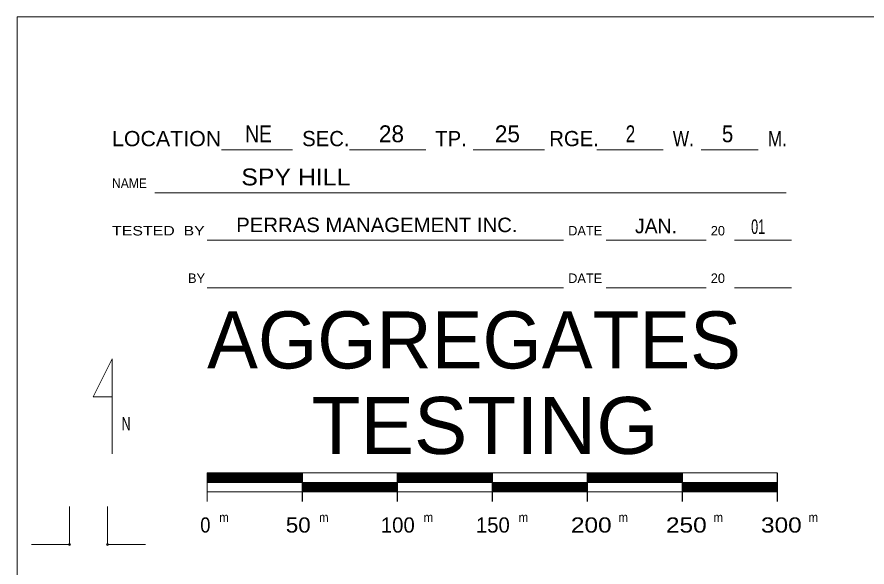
# Model space of a CAD drawing. Extents: x -496 to 480, y -452 to 700.
# Drawn here: x -450 to -2.8, y 410.5 to 700 of the extents above; entities that cross this region are included whole.
import ezdxf
from ezdxf.enums import TextEntityAlignment as Align

# ---------------------------------------------------------------- set-up
doc = ezdxf.new("R2010")
doc.units = 0
doc.header["$LTSCALE"] = 2
doc.header["$PDMODE"] = 32
doc.header["$PDSIZE"] = 1
doc.layers.add('3', color=7, linetype='Continuous', lineweight=13)

msp = doc.modelspace()

# ---------------------------------------------------------------- linework, layer by layer
at = {"layer": '3'}
for p, q in [((-342.517, 629.973), (-305.017, 629.973)), ((-275.017, 629.973), (-235.017, 629.973)), ((-210.017, 629.973), (-172.517, 629.973)), ((-145.017, 629.973), (-110.017, 629.973)), ((-90.017, 629.973), (-60.017, 629.973)), ((-377.517, 607.473), (-45.359, 607.473)), ((-350.017, 582.473), (-162.517, 582.473)), ((-140.017, 582.473), (-87.517, 582.473)), ((-72.517, 582.473), (-42.517, 582.473)), ((-350.017, 557.473), (-162.517, 557.473)), ((-140.017, 557.473), (-87.517, 557.473)), ((-72.517, 557.473), (-42.517, 557.473)), ((-350.017, 459.973), (-350.017, 444.973)), ((-50.017, 459.973), (-350.017, 459.973)), ((-350.017, 454.973), (-50.017, 454.973)), ((-422.391, 422.339), (-422.391, 442.339)), ((-402.391, 422.339), (-402.391, 442.339)), ((-422.391, 422.339), (-442.391, 422.339))]:
    msp.add_line(p, q, dxfattribs=at)
at = {"layer": '3', "lineweight": 25}
for p, q in [((-350.017, 459.473), (-300.017, 459.473)), ((-350.017, 458.973), (-300.017, 458.973)), ((-350.017, 458.473), (-300.017, 458.473)), ((-350.017, 457.973), (-300.017, 457.973)), ((-350.017, 457.473), (-300.017, 457.473)), ((-350.017, 456.973), (-300.017, 456.973)), ((-350.017, 456.473), (-300.017, 456.473)), ((-350.017, 456.473), (-300.017, 456.473)), ((-350.017, 456.473), (-300.017, 456.473)), ((-300.017, 459.973), (-300.017, 444.973)), ((-250.017, 459.973), (-250.017, 444.973)), ((-250.017, 459.473), (-200.017, 459.473)), ((-250.017, 458.973), (-200.017, 458.973)), ((-250.017, 458.473), (-200.017, 458.473)), ((-250.017, 457.973), (-200.017, 457.973)), ((-250.017, 457.473), (-200.017, 457.473)), ((-250.017, 456.973), (-200.017, 456.973)), ((-250.017, 456.473), (-200.017, 456.473)), ((-200.017, 459.973), (-200.017, 444.973)), ((-150.017, 459.973), (-150.017, 444.973)), ((-150.017, 459.473), (-100.017, 459.473)), ((-150.017, 458.973), (-100.017, 458.973)), ((-150.017, 458.473), (-100.017, 458.473)), ((-150.017, 457.973), (-100.017, 457.973)), ((-150.017, 457.473), (-100.017, 457.473)), ((-150.017, 456.973), (-100.017, 456.973)), ((-150.017, 456.473), (-100.017, 456.473)), ((-100.017, 459.973), (-100.017, 444.973)), ((-50.017, 459.973), (-50.017, 444.973)), ((-350.017, 455.973), (-300.017, 455.973)), ((-350.017, 455.973), (-300.017, 455.973)), ((-350.017, 455.473), (-300.017, 455.473)), ((-300.017, 454.473), (-250.017, 454.473)), ((-300.017, 453.973), (-250.017, 453.973)), ((-300.017, 453.473), (-250.017, 453.473)), ((-300.017, 452.973), (-250.017, 452.973)), ((-300.017, 452.473), (-250.017, 452.473)), ((-300.017, 451.973), (-250.017, 451.973)), ((-250.017, 455.973), (-200.017, 455.973)), ((-250.017, 455.473), (-200.017, 455.473)), ((-200.017, 454.473), (-150.017, 454.473)), ((-200.017, 453.973), (-150.017, 453.973)), ((-200.017, 453.473), (-150.017, 453.473)), ((-200.017, 452.973), (-150.017, 452.973)), ((-200.017, 452.473), (-150.017, 452.473)), ((-200.017, 451.973), (-150.017, 451.973)), ((-150.017, 455.973), (-100.017, 455.973)), ((-150.017, 455.473), (-100.017, 455.473)), ((-100.017, 454.473), (-50.017, 454.473)), ((-100.017, 453.973), (-50.017, 453.973)), ((-100.017, 453.473), (-50.017, 453.473)), ((-100.017, 452.973), (-50.017, 452.973)), ((-100.017, 452.473), (-50.017, 452.473)), ((-100.017, 451.973), (-50.017, 451.973)), ((-300.017, 451.473), (-250.017, 451.473)), ((-300.017, 450.973), (-250.017, 450.973)), ((-300.017, 450.473), (-250.017, 450.473)), ((-200.017, 451.473), (-150.017, 451.473)), ((-200.017, 450.973), (-150.017, 450.973)), ((-200.017, 450.473), (-150.017, 450.473)), ((-100.017, 451.473), (-50.017, 451.473)), ((-100.017, 450.973), (-50.017, 450.973)), ((-100.017, 450.473), (-50.017, 450.473))]:
    msp.add_line(p, q, dxfattribs=at)
at = {"layer": '3'}
for points in [[(449.983, -450.027), (449.983, 399.973), (449.983, 699.973), (-450.017, 699.973), (-450.017, 49.973), (-450.017, -450.027)], [(-400.017, 469.973), (-400.017, 519.973), (-410.017, 499.973), (-400.017, 499.973)], [(-350.017, 449.973), (-50.017, 449.973), (-50.017, 459.973)], [(-402.391, 422.339), (-382.391, 422.339), (-402.391, 422.339)]]:
    msp.add_lwpolyline(points, dxfattribs=at)
for p in [(-422.391, 422.339), (-402.391, 422.339)]:
    msp.add_point(p, dxfattribs=at)

# ---------------------------------------------------------------- texts
for s, height, width, p in [('LOCATION', 8, 1.05, (-400.017, 631.973)), ('W.', 8, 0.85, (-105.017, 631.973)), ('M.', 8, 0.85, (-55.017, 631.973)), ('NAME', 5, 0.95, (-400.017, 609.973)), ('TESTED  BY', 5, 1.25, (-400.017, 584.973)), ('TESTING', 30, 1.05, (-295.017, 469.973)), ('N', 7, 0.7, (-395.017, 482.473)), ('0', 8, 0.9, (-353.607, 428.573)), ('m', 5, 0.9, (-343.607, 434.073)), ('50', 8, 1.1, (-308.607, 428.573)), ('m', 5, 0.9, (-291.107, 434.073)), ('m', 5, 0.9, (-236.107, 434.073)), ('m', 5, 0.9, (-186.107, 434.073)), ('200', 8, 1.2, (-158.607, 428.573)), ('m', 5, 0.9, (-133.607, 434.073)), ('250', 8, 1.2, (-108.607, 428.573)), ('m', 5, 0.9, (-83.607, 434.073)), ('300', 8, 1.2, (-58.607, 428.573)), ('m', 5, 0.9, (-33.607, 434.073))]:
    msp.add_text(s, height=height, dxfattribs=dict(at, width=width)).set_placement(p)
for s, height, width, p in [('NE', 8.89, 0.85, (-322.943, 634.038)), ('2', 8.89, 0.75, (-127.28, 634.037)), ('5', 8.89, 0.9, (-76.181, 634.038)), ('SPY HILL', 8.89, 1.1, (-303.323, 611.329)), ('PERRAS MANAGEMENT INC.', 7.62, 1.05, (-260.682, 586.728)), ('01', 7.62, 0.65, (-60.119, 585.781))]:
    msp.add_text(s, height=height, dxfattribs=dict(at, width=width)).set_placement(p, align=Align.CENTER)
for s, height, p in [('SEC.', 8, (-300.017, 631.973)), ('TP.', 8, (-230.017, 631.973)), ('RGE.', 8, (-170.017, 631.973)), ('DATE', 5, (-160.017, 584.973)), ('20', 5, (-85.017, 584.973)), ('BY', 5, (-360.017, 559.973)), ('DATE', 5, (-160.017, 559.973)), ('20', 5, (-85.017, 559.973)), ('AGGREGATES', 30, (-350.017, 514.973)), ('100', 8, (-258.607, 428.573)), ('150', 8, (-208.607, 428.573))]:
    msp.add_text(s, height=height, dxfattribs=at).set_placement(p)
for s, height, p in [('28', 8.89, (-253.021, 634.038)), ('25', 8.89, (-192.027, 634.038)), ('JAN.', 7.62, (-113.875, 586.148))]:
    msp.add_text(s, height=height, dxfattribs=at).set_placement(p, align=Align.CENTER)

doc.saveas('drawing.dxf')
